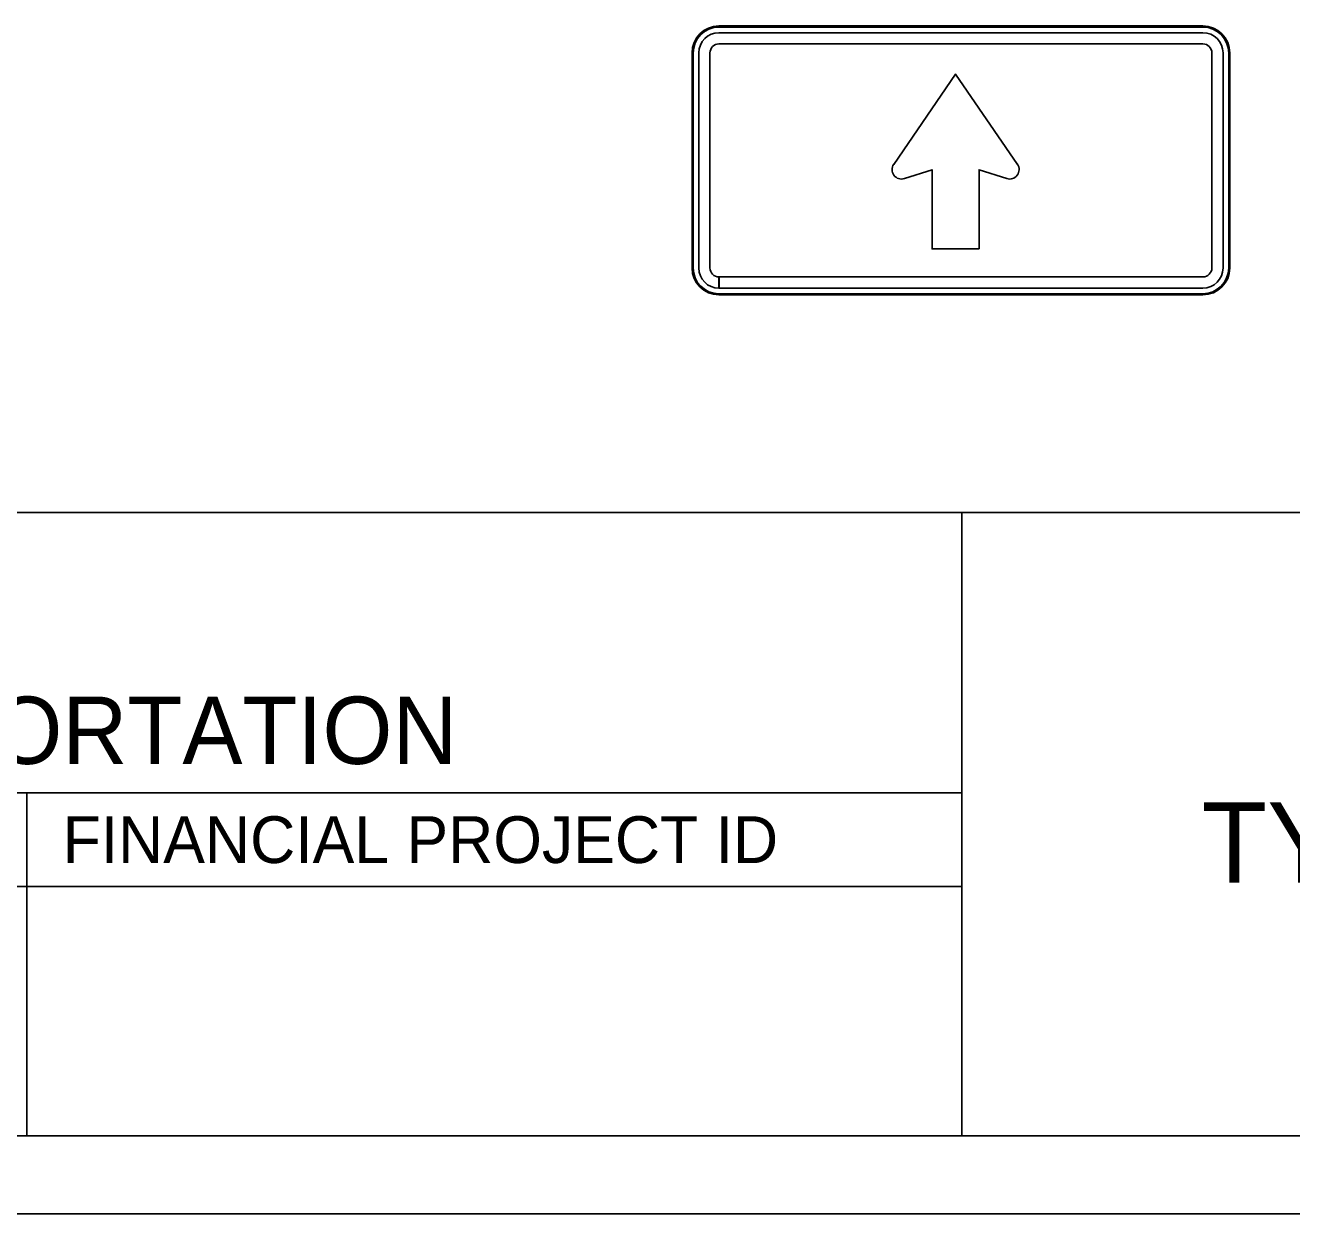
# Model space of a CAD drawing. Extents: x 17890587 to 17890754, y 17897693 to 17897992.
# Drawn here: x 17890617.41 to 17890622.178, y 17897873.104 to 17897877.578 of the extents above; entities that cross this region are included whole.
import ezdxf

# ---------------------------------------------------------------- set-up
doc = ezdxf.new("R2010")
doc.units = 0
for name, color, linetype in [('GSColorFill', 7, 'Continuous'), ('PlotBorder_dp', 7, 'Continuous'), ('SheetBorder_dp', 7, 'Continuous'), ('SheetLines_dp', 7, 'Continuous'), ('TextMisc', 7, 'Continuous')]:
    doc.layers.add(name, color=color, linetype=linetype)

msp = doc.modelspace()

# ---------------------------------------------------------------- linework, layer by layer
at = {"layer": 'GSColorFill'}
for p, q in [((17890621.8437, 17897877.5759), (17890620.0214, 17897877.5759)), ((17890621.8437, 17897877.5759), (17890620.0214, 17897877.5759)), ((17890620.0214, 17897877.5717), (17890621.8437, 17897877.5717)), ((17890621.8437, 17897877.5506), (17890620.0214, 17897877.5506)), ((17890620.0214, 17897877.5084), (17890621.8437, 17897877.5084)), ((17890619.9202, 17897877.4746), (17890619.9202, 17897876.6647)), ((17890619.9202, 17897877.4746), (17890619.9202, 17897876.6647)), ((17890619.9244, 17897876.6647), (17890619.9244, 17897877.4746)), ((17890619.9455, 17897877.4746), (17890619.9455, 17897876.6647)), ((17890619.9877, 17897876.6647), (17890619.9877, 17897877.4746)), ((17890621.8775, 17897877.4746), (17890621.8775, 17897876.6647)), ((17890621.9197, 17897876.6647), (17890621.9197, 17897877.4746)), ((17890621.9408, 17897877.4746), (17890621.9408, 17897876.6647)), ((17890621.945, 17897876.6647), (17890621.945, 17897877.4746)), ((17890621.945, 17897876.6647), (17890621.945, 17897877.4746)), ((17890620.0214, 17897876.5888), (17890620.0214, 17897876.631)), ((17890621.8437, 17897876.631), (17890620.0218, 17897876.631)), ((17890620.0218, 17897876.631), (17890620.0218, 17897876.5888)), ((17890620.0214, 17897876.5635), (17890620.0214, 17897876.5677)), ((17890620.0214, 17897876.5635), (17890621.8437, 17897876.5635)), ((17890621.8437, 17897876.5677), (17890620.0215, 17897876.5677)), ((17890620.0215, 17897876.5677), (17890620.0215, 17897876.5635)), ((17890620.0215, 17897876.5635), (17890621.8437, 17897876.5635)), ((17890620.0218, 17897876.5888), (17890621.8437, 17897876.5888))]:
    msp.add_line(p, q, dxfattribs=at)
for points in [[(17890621.1456, 17897877.0549), (17890620.9126, 17897877.3945), (17890620.6796, 17897877.0549)], [(17890621.1456, 17897877.0549), (17890620.9126, 17897877.3945), (17890620.6796, 17897877.0549)], [(17890621.1456, 17897877.0549), (17890620.9126, 17897877.3945), (17890620.6796, 17897877.0549)], [(17890620.7195, 17897877.0011), (17890620.824, 17897877.0343), (17890620.824, 17897876.7365), (17890621.0011, 17897876.7365)], [(17890620.7195, 17897877.0011), (17890620.824, 17897877.0343), (17890620.824, 17897876.7365), (17890621.0011, 17897876.7365)], [(17890620.7195, 17897877.0011), (17890620.824, 17897877.0343), (17890620.824, 17897876.7365), (17890621.0011, 17897876.7365)], [(17890621.0011, 17897876.7365), (17890621.0011, 17897877.0343), (17890621.1056, 17897877.0011)], [(17890621.0011, 17897876.7365), (17890621.0011, 17897877.0343), (17890621.1056, 17897877.0011)], [(17890621.0011, 17897876.7365), (17890621.0011, 17897877.0343), (17890621.1056, 17897877.0011)]]:
    msp.add_lwpolyline(points, dxfattribs=at)
for centre, radius, start, end in [((17890620.0214, 17897877.4746), 0.1012, 90, 180), ((17890620.0214, 17897877.4746), 0.1012, 90, 180), ((17890620.0214, 17897877.4746), 0.097, 90, 180), ((17890620.0214, 17897877.4746), 0.0759, 90, 180), ((17890621.8437, 17897877.4746), 0.1012, 0, 90), ((17890621.8437, 17897877.4746), 0.1012, 0, 90), ((17890621.8437, 17897877.4746), 0.097, 0, 90), ((17890621.8437, 17897877.4746), 0.0759, 0, 90), ((17890620.0214, 17897877.4746), 0.0337, 90, 180), ((17890621.8437, 17897877.4746), 0.0337, 0, 90), ((17890620.0214, 17897876.6647), 0.1012, 180, 270), ((17890620.0214, 17897876.6647), 0.1012, 180, 270), ((17890620.0214, 17897876.6647), 0.097, 180, 270), ((17890620.0214, 17897876.6647), 0.0759, 180, 270), ((17890620.0214, 17897876.6647), 0.0337, 180, 270), ((17890621.8437, 17897876.6647), 0.1012, 270, 0), ((17890621.8437, 17897876.6647), 0.1012, 270, 0), ((17890621.8437, 17897876.6647), 0.097, 270, 0), ((17890621.8437, 17897876.6647), 0.0759, 270, 0), ((17890621.8437, 17897876.6647), 0.0337, 270, 0)]:
    msp.add_arc(centre, radius, start, end, dxfattribs=at)
for centre, start_param, end_param in [((17890620.7088, 17897877.0349), 5.681933, 8.161176), ((17890620.7088, 17897877.0349), 5.681933, 8.161176), ((17890620.7088, 17897877.0349), 5.681933, 8.161176), ((17890621.1163, 17897877.0349), 1.263602, 3.742845), ((17890621.1163, 17897877.0349), 1.263602, 3.742845), ((17890621.1163, 17897877.0349), 1.263602, 3.742845)]:
    msp.add_ellipse(centre, major_axis=(-0.0354, 0), ratio=0.999949, start_param=start_param, end_param=end_param, dxfattribs=at)
at = {"layer": 'PlotBorder_dp'}
msp.add_lwpolyline([(17890586.7562, 17897873.1039), (17890635.165, 17897873.1039), (17890635.165, 17897904.2029), (17890586.7562, 17897904.2029)], close=True, dxfattribs=at)
at = {"layer": 'SheetBorder_dp'}
for p, q in [((17890588.3699, 17897875.7444), (17890633.5514, 17897875.7444)), ((17890588.3699, 17897873.3973), (17890633.5514, 17897873.3973))]:
    msp.add_line(p, q, dxfattribs=at)
at = {"layer": 'SheetLines_dp'}
for p, q in [((17890620.9358, 17897873.3973), (17890620.9358, 17897875.7444)), ((17890612.1342, 17897874.6882), (17890620.9358, 17897874.6882)), ((17890617.4151, 17897874.6882), (17890617.4151, 17897873.3973)), ((17890612.1342, 17897874.3361), (17890620.9358, 17897874.3361))]:
    msp.add_line(p, q, dxfattribs=at)

# ---------------------------------------------------------------- texts
at = {"layer": 'TextMisc'}
for s, height, p in [('DEPARTMENT OF TRANSPORTATION', 0.253486, (17890612.9166, 17897874.7972)), ('TYPICAL TRAILBLAZING SIGNS', 0.302553, (17890621.8386, 17897874.3505)), ('FINANCIAL PROJECT ID', 0.176032, (17890617.55, 17897874.4242))]:
    msp.add_text(s, height=height, dxfattribs=at).set_placement(p)

doc.saveas('drawing.dxf')
